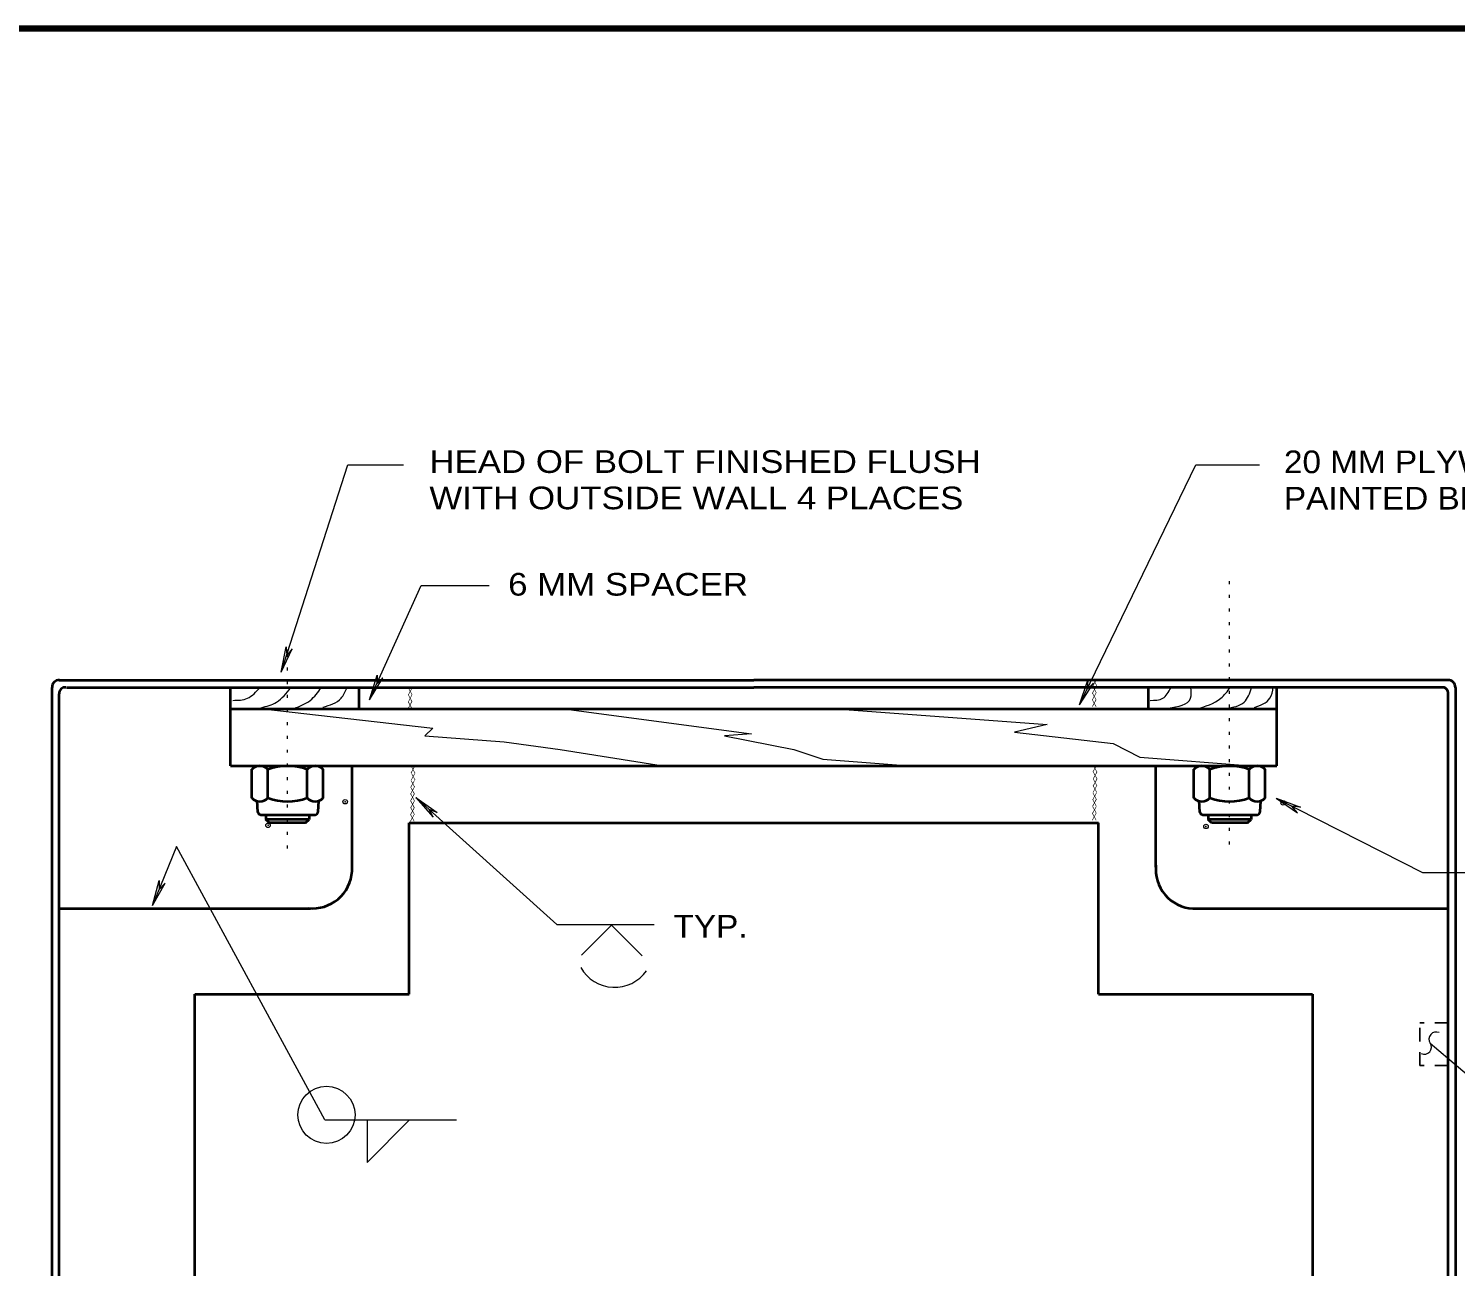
# Model space of a CAD drawing. Extents: x 312583 to 312853, y 144420 to 144585.
# Drawn here: x 312762.64 to 312810.54, y 144543.53 to 144585.08 of the extents above; entities that cross this region are included whole.
import ezdxf

# ---------------------------------------------------------------- set-up
doc = ezdxf.new("R2010")
doc.units = 0
doc.header["$LTSCALE"] = 0.3
doc.header["$PDMODE"] = 32
doc.header["$PDSIZE"] = 0.15
doc.linetypes.add('DOTTED', pattern=[1.5, 0.3, -1.2])
doc.linetypes.add('SHORT_DASHED', pattern=[2.7, 1.5, -1.2])
doc.layers.add('1', color=7, linetype='Continuous', lineweight=40)
doc.layers.add('2', color=7, linetype='Continuous', lineweight=13)

msp = doc.modelspace()

# ---------------------------------------------------------------- linework, layer by layer
at = {"layer": '1', "linetype": 'DOTTED', "lineweight": 13}
for p, q in [((312802.9552, 144557.6924), (312802.9552, 144566.5704)), ((312771.3302, 144557.5544), (312771.3302, 144564.3088))]:
    msp.add_line(p, q, dxfattribs=at)
at = {"layer": '1'}
for p, q in [((312770.1342, 144559.2488), (312770.1342, 144560.2148)), ((312770.6709, 144559.2488), (312770.6709, 144560.2148)), ((312771.9896, 144559.2488), (312771.9896, 144560.2148)), ((312771.9896, 144559.2488), (312771.9896, 144560.2148)), ((312772.5339, 144559.2488), (312772.5339, 144560.2148)), ((312801.7592, 144559.2488), (312801.7592, 144560.2148)), ((312802.2959, 144559.2488), (312802.2959, 144560.2148)), ((312803.6146, 144559.2488), (312803.6146, 144560.2148)), ((312803.6146, 144559.2488), (312803.6146, 144560.2148)), ((312804.1589, 144559.2488), (312804.1589, 144560.2148)), ((312770.3336, 144558.7811), (312770.3106, 144559.1644)), ((312801.9586, 144558.7811), (312801.9356, 144559.1644)), ((312772.2579, 144558.6814), (312770.4409, 144558.6814)), ((312770.6096, 144558.6891), (312770.6096, 144558.5358)), ((312772.0586, 144558.6814), (312772.0586, 144558.5358)), ((312772.3576, 144558.7964), (312772.3882, 144559.1414)), ((312803.8829, 144558.6814), (312802.0659, 144558.6814)), ((312802.2346, 144558.6891), (312802.2346, 144558.5358)), ((312803.6836, 144558.6814), (312803.6836, 144558.5358)), ((312803.9826, 144558.7964), (312804.0132, 144559.1414)), ((312770.7322, 144558.4131), (312770.6096, 144558.5358)), ((312772.0586, 144558.5358), (312770.6096, 144558.5358)), ((312771.9359, 144558.4131), (312770.7322, 144558.4131)), ((312771.9359, 144558.4131), (312772.0586, 144558.5358)), ((312802.3572, 144558.4131), (312802.2346, 144558.5358)), ((312803.6836, 144558.5358), (312802.2346, 144558.5358)), ((312803.5609, 144558.4131), (312802.3572, 144558.4131)), ((312803.5609, 144558.4131), (312803.6836, 144558.5358))]:
    msp.add_line(p, q, dxfattribs=at)
at = {"layer": '1', "lineweight": 158}
msp.add_lwpolyline([(312616.5, 144423.1446), (312616.5, 144585.0846), (312849, 144585.0846)], dxfattribs=at)
at = {"layer": '1'}
for centre, radius, start, end in [((312770.4054, 144559.9687), 0.363, 42.07502, 137.92498), ((312771.3334, 144558.4607), 1.871, 69.39031, 110.60969), ((312772.2614, 144559.9687), 0.363, 42.07502, 137.92498), ((312802.0304, 144559.9687), 0.363, 42.07502, 137.92498), ((312802.9584, 144558.4607), 1.871, 69.39031, 110.60969), ((312803.8864, 144559.9687), 0.363, 42.07502, 137.92498), ((312770.4054, 144559.4972), 0.363, 222.07502, 317.92498), ((312771.3334, 144561.0053), 1.871, 249.39031, 290.60969), ((312772.2614, 144559.4972), 0.363, 222.07502, 317.92498), ((312802.0304, 144559.4972), 0.363, 222.07502, 317.92498), ((312802.9584, 144561.0053), 1.871, 249.39031, 290.60969), ((312803.8864, 144559.4972), 0.363, 222.07502, 317.92498), ((312770.4698, 144558.8221), 0.1422, 196.73817, 261.43306), ((312772.2169, 144558.8176), 0.1422, 286.73817, 351.43306), ((312802.0948, 144558.8221), 0.1422, 196.73817, 261.43306), ((312803.8419, 144558.8176), 0.1422, 286.73817, 351.43306), ((312772.1785, 144556.8691), 1.3235, 263.7996, 356.80746), ((312801.8023, 144556.8595), 1.3235, 173.7996, 266.80746)]:
    msp.add_arc(centre, radius, start, end, dxfattribs=at)
at = {"layer": '2'}
for p, q in [((312771.1232, 144563.4731), (312773.3619, 144570.4421)), ((312773.3619, 144570.4421), (312775.2249, 144570.4421)), ((312797.9182, 144562.3768), (312801.8282, 144570.4421)), ((312801.8282, 144570.4421), (312803.9672, 144570.4421)), ((312774.0826, 144562.5454), (312775.8229, 144566.3864)), ((312775.8229, 144566.3864), (312778.0999, 144566.3864)), ((312771.1232, 144563.4731), (312771.2842, 144564.3318)), ((312771.1232, 144563.4731), (312771.4912, 144564.2628)), ((312771.2842, 144564.3318), (312771.3072, 144564.0328)), ((312771.4912, 144564.2628), (312771.3072, 144564.0328)), ((312774.0826, 144562.5454), (312774.3432, 144563.3811)), ((312774.0826, 144562.5454), (312774.5349, 144563.2891)), ((312774.3432, 144563.3811), (312774.3279, 144563.0821)), ((312774.5349, 144563.2891), (312774.3279, 144563.0821)), ((312797.9182, 144562.3768), (312798.2019, 144563.2048)), ((312797.9182, 144562.3768), (312798.3936, 144563.1128)), ((312798.2019, 144563.2048), (312798.1789, 144562.9058)), ((312798.3936, 144563.1128), (312798.1789, 144562.9058)), ((312775.6466, 144559.2641), (312776.2216, 144558.6048)), ((312775.6466, 144559.2641), (312776.3596, 144558.7658)), ((312804.5192, 144559.2488), (312809.4336, 144556.7494)), ((312804.5192, 144559.2488), (312805.2399, 144558.7581)), ((312804.5192, 144559.2488), (312805.3396, 144558.9498)), ((312776.2216, 144558.6048), (312776.0836, 144558.8654)), ((312776.3596, 144558.7658), (312776.0836, 144558.8654)), ((312805.2399, 144558.7581), (312805.0482, 144558.9804)), ((312805.3396, 144558.9498), (312805.0482, 144558.9804)), ((312766.7992, 144555.6378), (312767.0216, 144556.4811)), ((312766.7992, 144555.6378), (312767.2209, 144556.3968)), ((312767.0216, 144556.4811), (312767.0216, 144556.1821)), ((312767.2209, 144556.3968), (312767.0216, 144556.1821)), ((312809.4336, 144556.7494), (312813.6042, 144556.7494)), ((312781.2049, 144553.9741), (312782.2092, 144554.9784)), ((312783.2366, 144553.9511), (312782.2092, 144554.9784)), ((312809.6942, 144551.0224), (312812.3009, 144548.7991)), ((312772.5876, 144548.4464), (312777.0036, 144548.4464)), ((312774.0059, 144547.0128), (312775.4166, 144548.4388)), ((312774.0059, 144548.4388), (312774.0059, 144547.0128))]:
    msp.add_line(p, q, dxfattribs=at)
at = {"layer": '2', "lineweight": 40}
for p, q in [((312763.6712, 144563.2048), (312786.9856, 144563.2048)), ((312810.2999, 144563.2048), (312786.9856, 144563.2048)), ((312763.4336, 144540.9254), (312763.4336, 144562.9671)), ((312763.6712, 144540.9254), (312763.6712, 144562.7448)), ((312763.9089, 144562.9671), (312786.9856, 144562.9671)), ((312769.4212, 144562.2464), (312769.4212, 144562.9671)), ((312773.7376, 144562.2464), (312773.7376, 144562.9671)), ((312810.0776, 144562.9671), (312786.9856, 144562.9671)), ((312800.2412, 144562.2464), (312800.2412, 144562.9671)), ((312804.5499, 144562.2464), (312804.5499, 144562.9671)), ((312810.2999, 144540.9254), (312810.2999, 144562.7448)), ((312810.5376, 144562.9671), (312810.5376, 144518.8838)), ((312769.4212, 144562.2464), (312804.5499, 144562.2464)), ((312769.4212, 144560.3298), (312769.4212, 144562.2464)), ((312804.5499, 144560.3298), (312804.5499, 144562.2464)), ((312769.4212, 144560.3298), (312804.5499, 144560.3298)), ((312773.4999, 144556.7954), (312773.4999, 144560.3298)), ((312800.4789, 144556.9334), (312800.4789, 144560.3298)), ((312775.4166, 144558.4131), (312798.5622, 144558.4131)), ((312775.4166, 144552.6631), (312775.4166, 144558.4131)), ((312798.5622, 144552.6631), (312798.5622, 144558.4131)), ((312763.6712, 144555.5381), (312772.1046, 144555.5381)), ((312801.7286, 144555.5381), (312810.2999, 144555.5381)), ((312768.2252, 144552.6631), (312775.4166, 144552.6631)), ((312768.2252, 144529.1878), (312768.2252, 144552.6631)), ((312798.5622, 144552.6631), (312805.7459, 144552.6631)), ((312805.7459, 144552.6631), (312805.7459, 144529.1878))]:
    msp.add_line(p, q, dxfattribs=at)
at = {"layer": '2', "linetype": 'SHORT_DASHED', "lineweight": 25}
for p, q in [((312809.3416, 144550.2711), (312809.3416, 144551.7048)), ((312810.2999, 144551.7048), (312809.3416, 144551.7048)), ((312810.2999, 144550.2711), (312809.3416, 144550.2711))]:
    msp.add_line(p, q, dxfattribs=at)
at = {"layer": '2'}
for points in [[(312770.5022, 144562.2464), (312776.2062, 144561.5948), (312775.9456, 144561.3418), (312778.6059, 144561.1424), (312780.4842, 144560.8818), (312783.7272, 144560.3681)], [(312780.6146, 144562.2464), (312786.9089, 144561.4031), (312786.0042, 144561.3418), (312788.3349, 144560.8818), (312789.3086, 144560.5598), (312791.7772, 144560.3681)], [(312789.7456, 144562.2464), (312796.8372, 144561.7251), (312795.7332, 144561.4644), (312799.0452, 144561.0811), (312799.9499, 144560.6211), (312803.6989, 144560.3298)], [(312775.6466, 144559.2641), (312780.3692, 144555.0091), (312783.6429, 144555.0091)], [(312772.5876, 144548.4464), (312767.6042, 144557.6234), (312766.7992, 144555.6378)]]:
    msp.add_lwpolyline(points, dxfattribs=at)
msp.add_circle((312772.6412, 144548.6151), 0.9583, dxfattribs=at)
at = {"layer": '2', "lineweight": 40}
for centre, radius, start, end in [((312763.657, 144562.9813), 0.2239, 84.40066, 183.64627), ((312810.3141, 144562.9813), 0.2239, 356.35373, 95.59934), ((312763.8706, 144562.7678), 0.2007, 83.41806, 186.58194), ((312810.1006, 144562.7678), 0.2007, 353.41806, 96.58194)]:
    msp.add_arc(centre, radius, start, end, dxfattribs=at)
at = {"layer": '2'}
for centre, radius, start, end in [((312782.3157, 144554.195), 1.2994, 209.24945, 325.16514), ((312809.497, 144550.8867), 0.2394, 244.53777, 34.53777), ((312809.8914, 144551.1582), 0.2394, 64.53777, 214.53777)]:
    msp.add_arc(centre, radius, start, end, dxfattribs=at)
for points in [[(312800.9006, 144562.2694), (312801.6519, 144562.5991), (312801.6519, 144562.9901)], [(312769.4979, 144562.5301), (312769.9886, 144562.5991), (312770.4102, 144562.9671)], [(312770.4486, 144562.2848), (312770.9622, 144562.4688), (312771.4376, 144562.9594)], [(312771.5526, 144562.2618), (312772.0969, 144562.5301), (312772.4649, 144562.9594)], [(312772.5186, 144562.3001), (312773.1319, 144562.5991), (312773.3236, 144562.9364)], [(312800.2949, 144562.5301), (312800.7166, 144562.5991), (312800.9849, 144562.9518)], [(312801.8436, 144562.2388), (312802.6639, 144562.5991), (312802.9859, 144562.9671)], [(312802.8479, 144562.2618), (312803.4459, 144562.4688), (312803.6989, 144562.9594)], [(312803.7909, 144562.2924), (312804.3122, 144562.5991), (312804.4272, 144562.9748)]]:
    msp.add_spline(points, degree=3, dxfattribs=at)
for p in [(312773.2699, 144559.1261), (312804.7569, 144559.0878), (312770.6786, 144558.3364), (312802.1656, 144558.2981)]:
    msp.add_point(p, dxfattribs=at)

# ---------------------------------------------------------------- texts
at = {"layer": '1', "width": 0.7}
for height, p in [(0.23, (312798.3399, 144562.7754)), (0.23, (312798.3552, 144563.0131)), (0.23, (312775.3706, 144562.7141)), (0.2377, (312775.3706, 144562.4764)), (0.23, (312798.3322, 144562.5454)), (0.23, (312798.3322, 144562.3154)), (0.23, (312775.3629, 144562.2541)), (0.23, (312775.4626, 144560.0921)), (0.23, (312798.3552, 144560.1304)), (0.23, (312798.3629, 144559.8928)), (0.23, (312775.4549, 144559.6168)), (0.23, (312775.4702, 144559.8544)), (0.23, (312798.3552, 144559.4328)), (0.23, (312798.3629, 144559.6551)), (0.23, (312775.4472, 144559.3868)), (0.23, (312775.4472, 144559.1568)), (0.23, (312798.3399, 144558.9728)), (0.23, (312798.3476, 144559.1951)), (0.23, (312775.4396, 144558.4668)), (0.23, (312775.4472, 144558.9191)), (0.23, (312775.4472, 144558.6968)), (0.23, (312798.3322, 144558.5051)), (0.23, (312798.3399, 144558.7351))]:
    msp.add_text('X', height=height, dxfattribs=at).set_placement(p)
at = {"layer": '2'}
for s, width, p in [('HEAD OF BOLT FINISHED FLUSH', 1.15, (312776.0968, 144570.1661)), ('20 MM PLYWOOD (EXTERIOR GRADE)', 1.1, (312804.7834, 144570.1577)), ('WITH OUTSIDE WALL 4 PLACES', 1.15, (312776.0968, 144568.9461)), ('PAINTED BLACK', 1.1, (312804.7834, 144568.9377)), ('6 MM SPACER', 1.15, (312778.7396, 144566.0474)), ('TYP.', 1.1, (312784.2925, 144554.5651))]:
    msp.add_text(s, height=0.76, dxfattribs=dict(at, width=width)).set_placement(p)

doc.saveas('drawing.dxf')
